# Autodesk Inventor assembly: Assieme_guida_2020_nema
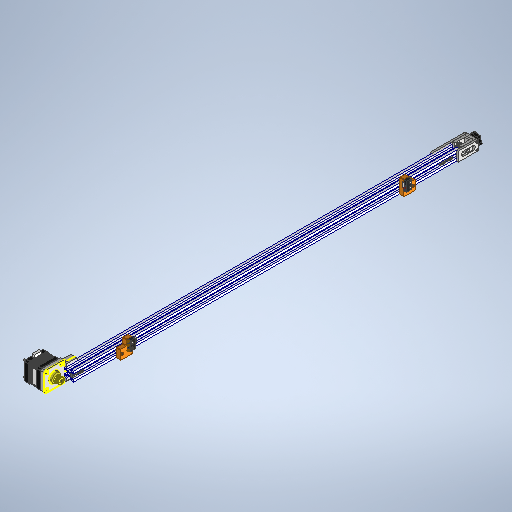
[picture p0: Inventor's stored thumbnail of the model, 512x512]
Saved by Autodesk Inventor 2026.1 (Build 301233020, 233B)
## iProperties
Created: 2026-01
Part Number: Assieme_guida_2020_nema
Document SubType Name: Assembly
Designer: hp
Sending System: Autodesk Inventor 2025
Preprocessor: ST-DEVELOPER v20
Title: Assieme_guida_2020_nema.stp
Author: R5800u
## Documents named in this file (18)
- C:\Users\hp\Documents\Inventor\DOM1_CartesianRobot\Assieme_guida_2020_nema.iam
- C:\Users\hp\Documents\Inventor\DOM1_CartesianRobot\2020.ipt
- C:\Users\hp\Documents\Inventor\DOM1_CartesianRobot\2020 Belt Tensioner G_K.iam
- C:\Users\hp\Documents\Inventor\DOM1_CartesianRobot\GT2_20T.ipt
- C:\Users\hp\Documents\Inventor\DOM1_CartesianRobot\NO-NC Limit Switch.ipt
- C:\Users\hp\Documents\Inventor\DOM1_CartesianRobot\blocco_sensore.ipt
- C:\Users\hp\Documents\Inventor\DOM1_CartesianRobot\blocco_sensore_MIR.ipt
- C:\Users\hp\Documents\Inventor\DOM1_CartesianRobot\NEMA 42SHDC3030Z.ipt
- C:\Users\hp\Documents\Inventor\DOM1_CartesianRobot\blocco_nema.ipt
- C:\Users\hp\Documents\Inventor\Content Center Files\R2026\en-US\ISO 4032(2)\ISO 4032 - M3 - ISO.ipt
- C:\Users\hp\Documents\Inventor\DOM1_CartesianRobot\2020 M3.ipt
- C:\Users\hp\Documents\Inventor\DOM1_CartesianRobot\2020 M4 (1).ipt
- C:\Users\hp\Documents\Inventor\Content Center Files\R2026\en-US\ISO 4017(1)\ISO 4017 - M2 x 16 - ISO.ipt
- C:\Users\hp\Documents\Inventor\Content Center Files\R2026\en-US\ISO 4035(2)\ISO 4035 - M2 - ISO.ipt
- C:\Users\hp\Documents\Inventor\Content Center Files\R2026\en-US\ISO 4017(1)\ISO 4017 - M4 x 25 - ISO.ipt
- C:\Users\hp\Documents\Inventor\Content Center Files\R2021\en-US\ANSI B18.3.1M(2)\ANSI B18.3.1M - M3x0.5 x 45(6).ipt
- C:\Users\hp\Documents\Inventor\Content Center Files\R2026\en-US\ISO 4762(2)\ISO 4762 - M4 x 25ISO.ipt
- C:\Users\hp\Documents\Inventor\Content Center Files\R2026\en-US\ISO 4762(2)\ISO 4762 - M3 x 25ISO.ipt
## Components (41 placed, 17 different names)
1. 2020:1
2. 2020 Belt Tensioner G_K:1 [sub-assembly]
3. GT2_20T:1 — Rigid:1
4. NO-NC Limit Switch:1
5. NO-NC Limit Switch:2
6. blocco_sensore:1 — Mate:6, Mate:9, Mate:10, Mate:11, Mate:57, Mate:59, Mate:106, Flush:2, Mate:113, Mate:114, Mate:115, Mate:116
7. blocco_sensore_MIR:1
8. NEMA 42SHDC3030Z:1 — Mate:1, Mate:2, Mate:3, Rigid:1, Mate:99, Mate:101, Mate:103, Mate:105
9. blocco_nema:1
10. 2020 M3:1 — Mate:63, Angle:3, Mate:118
11. 2020 M4 (1):1 — Mate:36, Angle:2, Mate:45, Mate:112
12. 2020 M3:2 — Mate:62, Angle:4, Mate:117
13. 2020 M4 (1):2 — Mate:44, Angle:1, Mate:111
14. ISO 4017 M2 x 16:1 — Mate:52, Mate:53
15. ISO 4035 M2:1 — Mate:56, Mate:57
16. ISO 4017 M2 x 16:2 — Mate:54, Mate:55
17. ISO 4035 M2:2 — Mate:58, Mate:59
18. ISO 4017 M4 x 25:1 — Mate:65, Mate:66, Mate:82
19. ISO 4017 M4 x 25:2 — Mate:67, Mate:68, Mate:81
20. ISO 4017 M2 x 16:3 — Mate:73, Mate:74
21. ISO 4035 M2:3 — Mate:77, Mate:78
22. ISO 4017 M2 x 16:4 — Mate:75, Mate:76
23. ISO 4035 M2:4 — Mate:79, Mate:80
24. 2020 M3:3 — Mate:88, Angle:9, Mate:124
25. 2020 M4 (1):3 — Mate:81, Mate:83, Angle:7
26. 2020 M4 (1):4 — Mate:82, Mate:84, Angle:6
27. 2020 M3:4 — Mate:89, Angle:8, Mate:123
28. Drilled Broached Hexagon Socket Head Cap Screw - 2 Holes - Metric M3x0.5 x 45:1 — Mate:90, Mate:91
29. ISO 4032 M3:1 — Mate:98, Mate:99
30. Drilled Broached Hexagon Socket Head Cap Screw - 2 Holes - Metric M3x0.5 x 45:2 — Mate:92, Mate:93
31. Drilled Broached Hexagon Socket Head Cap Screw - 2 Holes - Metric M3x0.5 x 45:3 — Mate:94, Mate:95
32. Drilled Broached Hexagon Socket Head Cap Screw - 2 Holes - Metric M3x0.5 x 45:4 — Mate:96, Mate:97
33. ISO 4032 M3:2 — Mate:100, Mate:101
34. ISO 4032 M3:3 — Mate:102, Mate:103
35. ISO 4032 M3:4 — Mate:104, Mate:105
36. ISO 4762 M4 x 25:1 — Mate:107, Mate:108, Mate:112
37. ISO 4762 M4 x 25:2 — Mate:109, Mate:110, Mate:111
38. ISO 4762 M3 x 25:1 — Mate:113, Mate:114, Mate:117
39. ISO 4762 M3 x 25:2 — Mate:115, Mate:116, Mate:118
40. ISO 4762 M3 x 25:3 — Mate:119, Mate:120, Mate:124
41. ISO 4762 M3 x 25:4 — Mate:121, Mate:122, Mate:123
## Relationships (83: Mate 73, Angle 8, WeldJoint 1, Flush 1)
- Mate:1: NEMA 42SHDC3030Z:1
- Mate:2: NEMA 42SHDC3030Z:1
- Mate:3: NEMA 42SHDC3030Z:1
- Rigid:1 [WeldJoint]: GT2_20T:1 ↔ NEMA 42SHDC3030Z:1
- Mate:6: blocco_sensore:1
- Mate:9: blocco_sensore:1
- Mate:10: blocco_sensore:1
- Mate:11: blocco_sensore:1
- Mate:36: 2020 M4 (1):1
- Mate:44: 2020 M4 (1):2
- Angle:1: 2020 M4 (1):2
- Angle:2: 2020 M4 (1):1
- Mate:45: 2020 M4 (1):1
- Mate:52: ISO 4017 M2 x 16:1
- Mate:53: ISO 4017 M2 x 16:1
- Mate:54: ISO 4017 M2 x 16:2
- Mate:55: ISO 4017 M2 x 16:2
- Mate:56: ISO 4035 M2:1
- Mate:57: blocco_sensore:1 ↔ ISO 4035 M2:1
- Mate:58: ISO 4035 M2:2
- Mate:59: blocco_sensore:1 ↔ ISO 4035 M2:2
- Mate:62: 2020 M3:2
- Mate:63: 2020 M3:1
- Angle:3: 2020 M3:1
- Angle:4: 2020 M3:2
- Mate:65: ISO 4017 M4 x 25:1
- Mate:66: ISO 4017 M4 x 25:1
- Mate:67: ISO 4017 M4 x 25:2
- Mate:68: ISO 4017 M4 x 25:2
- Mate:73: ISO 4017 M2 x 16:3
- Mate:74: ISO 4017 M2 x 16:3
- Mate:75: ISO 4017 M2 x 16:4
- Mate:76: ISO 4017 M2 x 16:4
- Mate:77: ISO 4035 M2:3
- Mate:78: ISO 4035 M2:3
- Mate:79: ISO 4035 M2:4
- Mate:80: ISO 4035 M2:4
- Mate:81: ISO 4017 M4 x 25:2 ↔ 2020 M4 (1):3
- Mate:82: ISO 4017 M4 x 25:1 ↔ 2020 M4 (1):4
- Mate:83: 2020 M4 (1):3
- Mate:84: 2020 M4 (1):4
- Angle:6: 2020 M4 (1):4
- Angle:7: 2020 M4 (1):3
- Mate:88: 2020 M3:3
- Mate:89: 2020 M3:4
- Angle:8: 2020 M3:4
- Angle:9: 2020 M3:3
- Mate:90: Drilled Broached Hexagon Socket Head Cap Screw - 2 Holes - Metric M3x0.5 x 45:1
- Mate:91: Drilled Broached Hexagon Socket Head Cap Screw - 2 Holes - Metric M3x0.5 x 45:1
- Mate:92: Drilled Broached Hexagon Socket Head Cap Screw - 2 Holes - Metric M3x0.5 x 45:2
- Mate:93: Drilled Broached Hexagon Socket Head Cap Screw - 2 Holes - Metric M3x0.5 x 45:2
- Mate:94: Drilled Broached Hexagon Socket Head Cap Screw - 2 Holes - Metric M3x0.5 x 45:3
- Mate:95: Drilled Broached Hexagon Socket Head Cap Screw - 2 Holes - Metric M3x0.5 x 45:3
- Mate:96: Drilled Broached Hexagon Socket Head Cap Screw - 2 Holes - Metric M3x0.5 x 45:4
- Mate:97: Drilled Broached Hexagon Socket Head Cap Screw - 2 Holes - Metric M3x0.5 x 45:4
- Mate:98: ISO 4032 M3:1
- Mate:99: NEMA 42SHDC3030Z:1 ↔ ISO 4032 M3:1
- Mate:100: ISO 4032 M3:2
- Mate:101: NEMA 42SHDC3030Z:1 ↔ ISO 4032 M3:2
- Mate:102: ISO 4032 M3:3
- Mate:103: NEMA 42SHDC3030Z:1 ↔ ISO 4032 M3:3
- Mate:104: ISO 4032 M3:4
- Mate:105: NEMA 42SHDC3030Z:1 ↔ ISO 4032 M3:4
- Mate:106: blocco_sensore:1
- Flush:2: blocco_sensore:1
- Mate:107: ISO 4762 M4 x 25:1
- Mate:108: ISO 4762 M4 x 25:1
- Mate:109: ISO 4762 M4 x 25:2
- Mate:110: ISO 4762 M4 x 25:2
- Mate:111: 2020 M4 (1):2 ↔ ISO 4762 M4 x 25:2
- Mate:112: 2020 M4 (1):1 ↔ ISO 4762 M4 x 25:1
- Mate:113: blocco_sensore:1 ↔ ISO 4762 M3 x 25:1
- Mate:114: blocco_sensore:1 ↔ ISO 4762 M3 x 25:1
- Mate:115: blocco_sensore:1 ↔ ISO 4762 M3 x 25:2
- Mate:116: blocco_sensore:1 ↔ ISO 4762 M3 x 25:2
- Mate:117: 2020 M3:2 ↔ ISO 4762 M3 x 25:1
- Mate:118: 2020 M3:1 ↔ ISO 4762 M3 x 25:2
- Mate:119: ISO 4762 M3 x 25:3
- Mate:120: ISO 4762 M3 x 25:3
- Mate:121: ISO 4762 M3 x 25:4
- Mate:122: ISO 4762 M3 x 25:4
- Mate:123: 2020 M3:4 ↔ ISO 4762 M3 x 25:4
- Mate:124: 2020 M3:3 ↔ ISO 4762 M3 x 25:3
